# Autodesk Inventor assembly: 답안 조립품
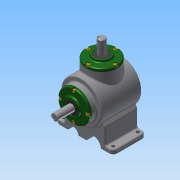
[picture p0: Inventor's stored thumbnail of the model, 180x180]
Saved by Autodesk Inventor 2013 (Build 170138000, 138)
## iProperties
Created: 2018-08
Part Number: 답안 조립품
Document SubType Name: Assembly
Designer: Administrator
Author: Administrator
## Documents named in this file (14)
- C:\Users\Administrator\Desktop\480808V1024\480808V1024\480808V1024\답안 조립품.iam
- C:\Users\Administrator\Desktop\480808V1024\480808V1024\480808V1024\본체.ipt
- C:\Users\Administrator\Desktop\480808V1024\480808V1024\480808V1024\메인 축.ipt
- 메인 축.ipt
- C:\Users\Administrator\Desktop\480808V1024\480808V1024\480808V1024\키 5x5.ipt
- C:\Users\Administrator\Desktop\480808V1024\480808V1024\480808V1024\메인 베벨기어.ipt
- C:\Users\Administrator\Desktop\480808V1024\480808V1024\480808V1024\베어링 6203.ipt
- C:\Users\Administrator\Desktop\480808V1024\480808V1024\480808V1024\커버.ipt
- C:\Users\Administrator\Desktop\480808V1024\480808V1024\480808V1024\오일실 17 32 8.ipt
- C:\Users\Administrator\Desktop\480808V1024\480808V1024\480808V1024\서브 축.ipt
- 서브 축.ipt
- C:\Users\Administrator\Desktop\480808V1024\480808V1024\480808V1024\서브 베벨기어.ipt
- C:\Users\Administrator\Desktop\480808V1024\480808V1024\480808V1024\키 4x4.ipt
- C:\Users\Administrator\Desktop\480808V1024\480808V1024\480808V1024\볼트 M4.ipt
